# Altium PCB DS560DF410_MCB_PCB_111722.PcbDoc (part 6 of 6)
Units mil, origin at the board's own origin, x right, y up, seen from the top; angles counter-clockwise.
Board outline 5500 x 5000 mil, 6 copper layers (Top Layer, L2_GND1, L3_SIG1, L4_PWR1, L5_GND2, Bottom Layer), stack 61.748 mil thick; 297 components, 231 nets, 1236 pads, 998 vias.
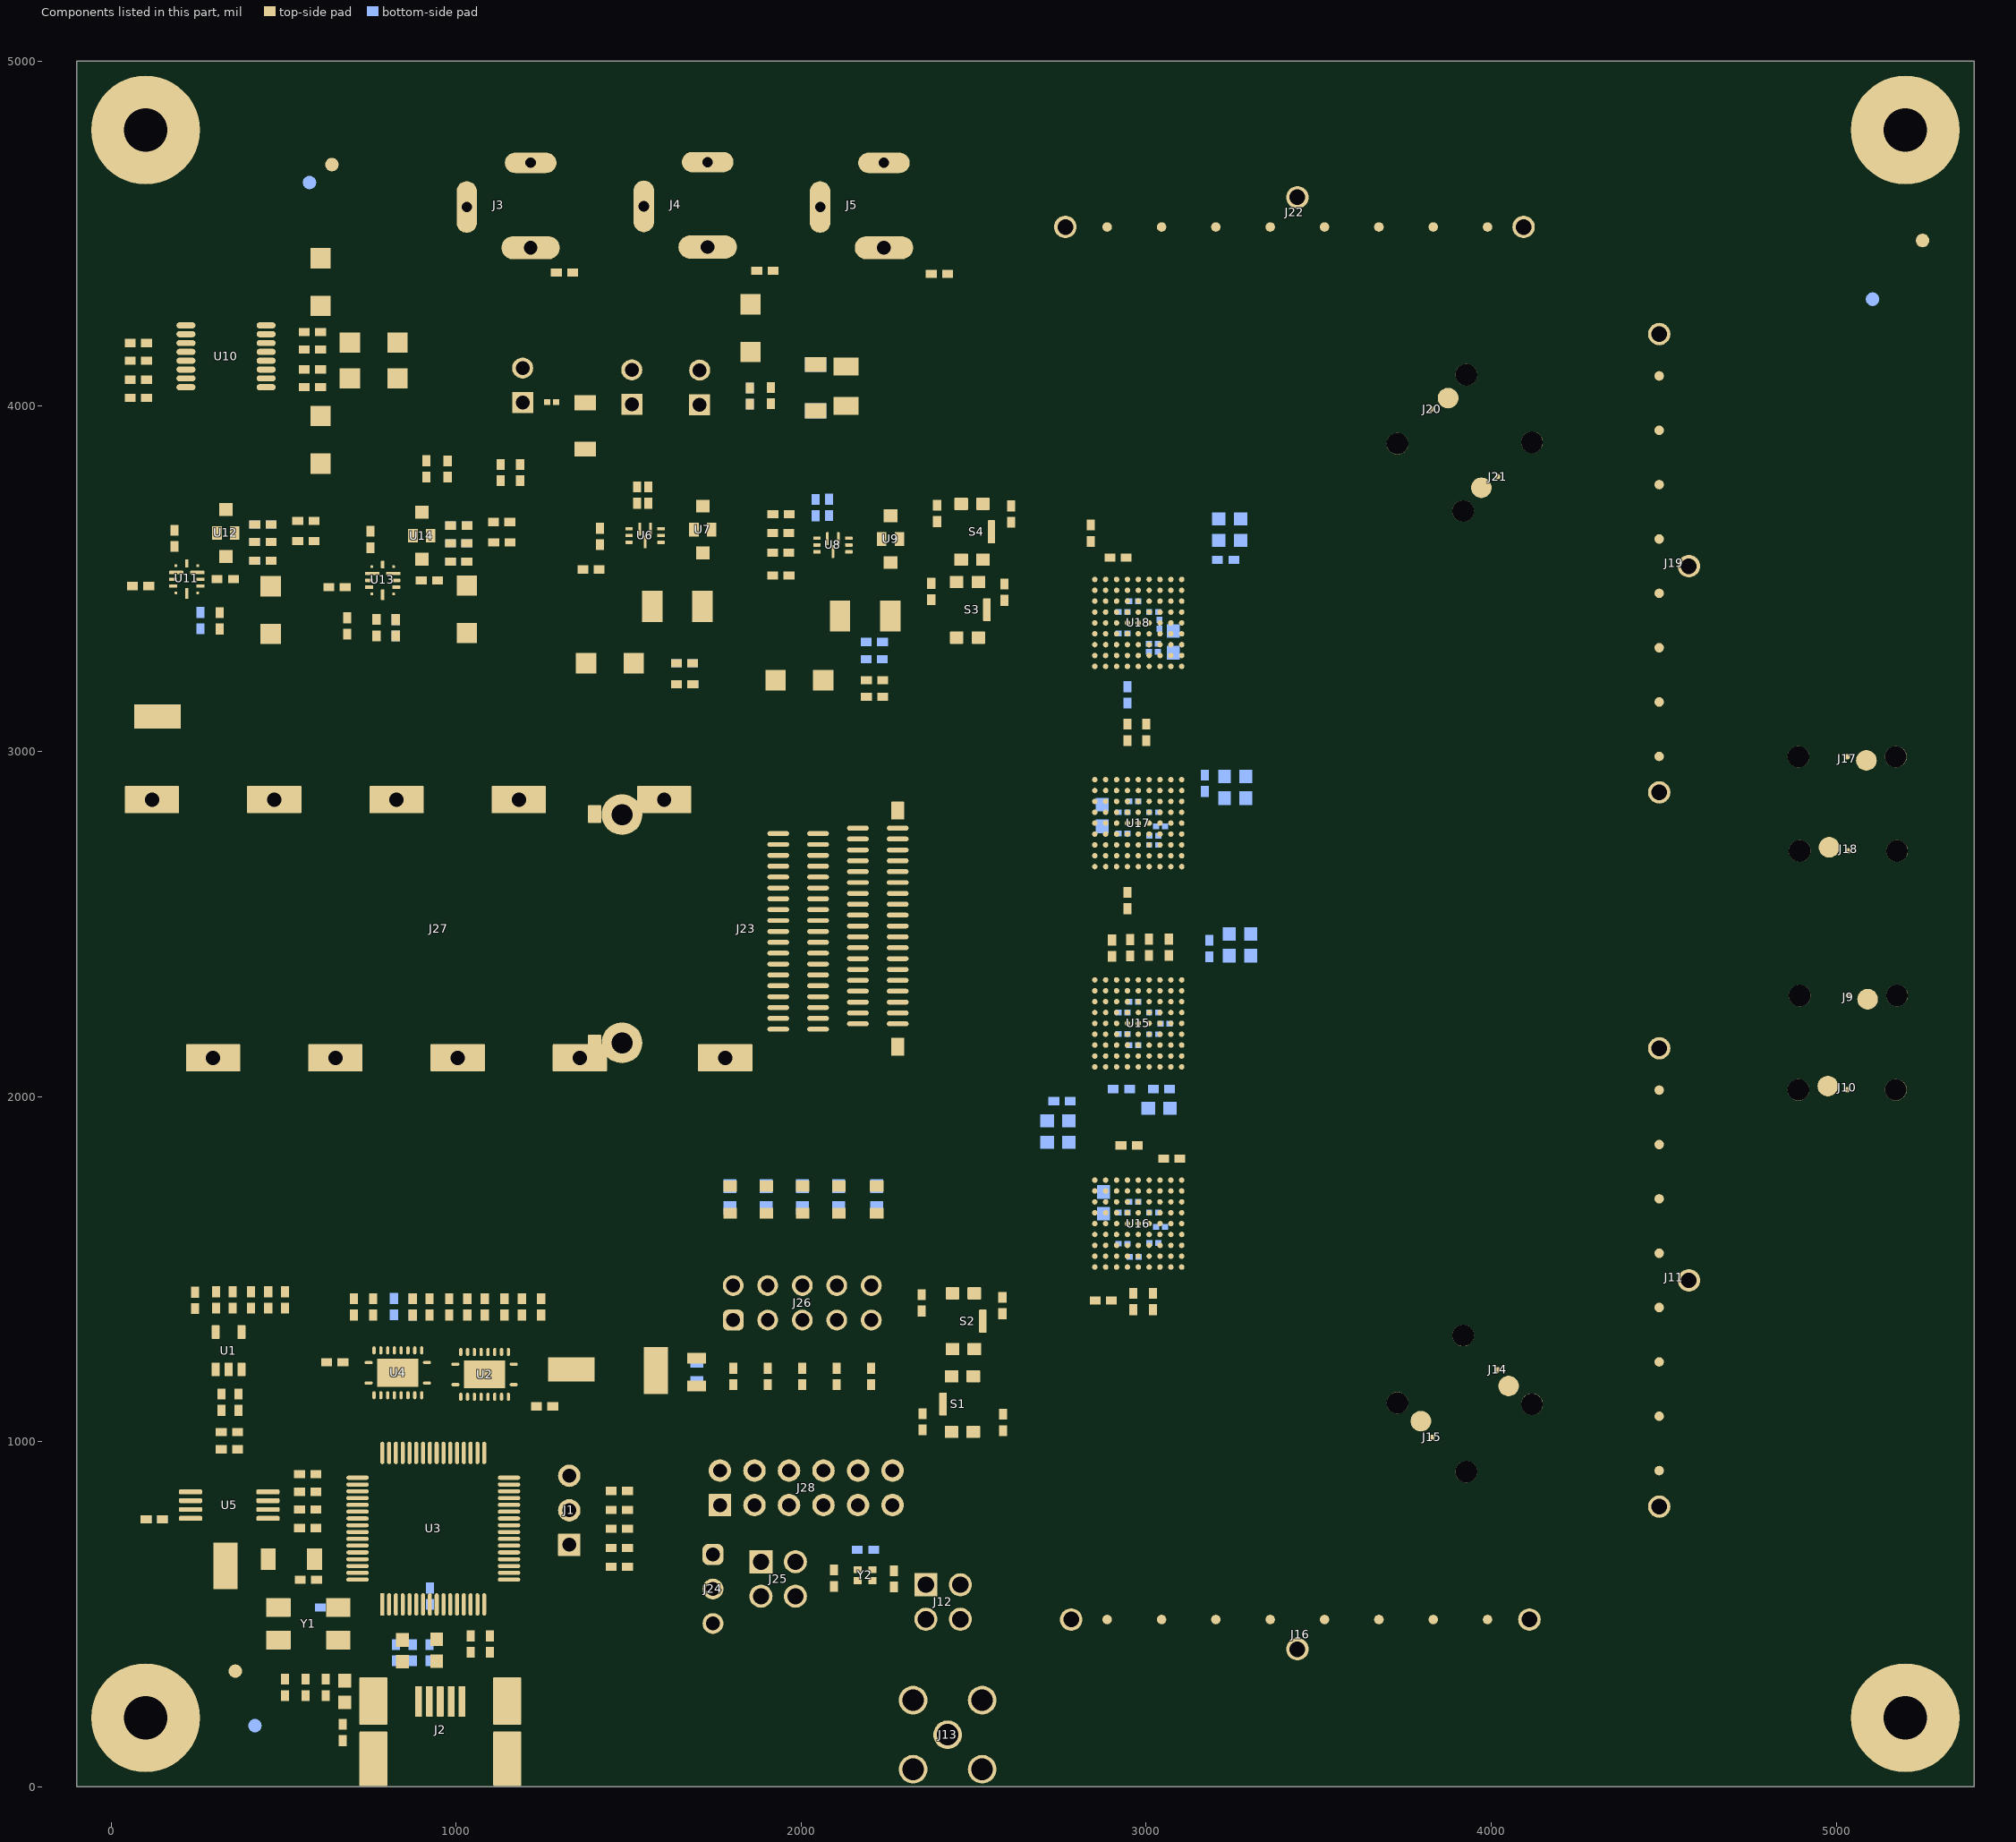
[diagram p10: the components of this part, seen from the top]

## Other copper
Top Layer:
  region net NetL3_1: 825.55,406.42 825.51,446.64 838.75,459.88 838.75,560.33 839.97,561.55 851.14,561.55 851.14,457.51 865.51,443.14 865.51,405.46 862.26,402.21 828.99,402.21 825.55,405.65
  region net 1P8V_CON: 1015.42,3642.39 1015.42,3685.52 1009.26,3691.68 1009.26,3707.28 1012.28,3710.3 1070.15,3710.3 1074.48,3705.97 1074.48,3659.07 1055.87,3640.46 1054.84,3641.5 1016.31,3641.5
  region net 1P2V_CON: 1622,3244.4 1621.9,3317.8 1630.1,3326 1649.6,3326 1656.92,3318.68 1656.92,3246.64 1653.07,3242.8 1623.6,3242.8
  region net VDD_1P8V_2: 894.9,1255.74 894.9,1273.45 907.35,1285.9 930.31,1285.9 935.96,1280.24 935.96,1263.16 925.33,1252.52 898.12,1252.52
  region net 3P3V_VPHY: 775.7,383.2 862.26,383.2 865.51,379.95 865.51,342.64 862.47,339.6 784.81,339.6 772.83,351.57 772.83,380.14 775.65,382.96
  region net 3P3V_VPLL: 924.3,383.2 924.3,324.37 937.66,311.01 952.6,311.01 963.34,321.76 963.34,382.96 959.5,386.8 927.88,386.8 924.29,383.2
  region net NetL4_1: 949.3,498.7 955,493 955,452.9 963.34,444.55 963.34,406.94 962.3,405.9 926.02,405.9 924.29,407.62 924.29,446.16 937.7,459.56 937.7,498.97 937.7,557.6 940.43,560.33 947.16,560.33 949.3,558.18
  region net 5V_USB: 899.4,198.9 845.72,198.9 837.95,206.68 837.95,288.12 845.5,295.67 897.93,295.67 902.2,291.4 902.2,201.7
  region net NetR46_2: 1123.22,3679.06 1094.52,3679.06 1091.02,3675.56 1091.02,3633.36 1076.72,3619.06 1017.32,3619.06 1013.52,3615.26 1013.52,3591.56 1015.92,3589.16 1122.92,3589.16 1128.12,3594.36 1128.12,3674.16
  region net NetC46_1: 829.12,3577.76 932.86,3577.76 947.71,3592.61 947.71,3664.41 955.3,3672 997.7,3672 1002.4,3667.3 1002.4,3536.24 997.22,3531.06 861.92,3531.06 839.62,3508.76 796.92,3508.76 795.92,3509.76 795.92,3521.96 807.52,3533.56 807.52,3556.16
  region net NetR37_2: 208.78,3512.24 168.08,3512.24 164.08,3516.24 164.08,3604.71 169.13,3609.75 195.67,3609.75 197.88,3607.54 197.88,3535.44 210.18,3523.14 210.18,3513.64
  region net NetR45_2: 776.4,3509 735.7,3509 731.7,3513 731.7,3601.47 736.74,3606.51 763.29,3606.51 765.5,3604.3 765.5,3532.2 777.8,3519.9 777.8,3510.4
  region net NetL7_1: 2076.26,3399.83 2076.26,3349.85 2082.58,3343.53 2141.96,3343.53 2146.36,3347.93 2146.36,3399.23 2146.35,3511.73 2096.75,3561.33 2096.76,3596.73 2095.05,3598.43 2088.96,3598.43 2087.36,3596.83 2087.36,3561.93 2076.26,3550.83
  region net NetC38_1: 2212.76,3470.23 2212.76,3145.73 2225.16,3133.33 2278.46,3133.33 2292.16,3147.03 2292.16,3558.23 2282.66,3567.73 2206.26,3567.73 2170.09,3603.89 2128.62,3603.89 2126.06,3601.33 2126.06,3556.93
  region net NetC31_1: 1395.96,4043.08 1538.32,4043.08 1546.1,4035.3 1546.1,3976.3 1537.7,3967.9 1475.2,3967.9 1457,3986.1 1287.1,3986.1 1280.46,3992.74 1280.46,4011.13 1280.46,4029.16 1294.38,4043.08
  region net NetJ7_1: 1265.5,4045.6 1163.2,4045.6 1157.8,4040.2 1157.8,3979.4 1163,3974.2 1262,3974.2 1273,3985.2 1273,4038.1
  region net NetR38_2: 555.6,3682.3 526.9,3682.3 523.4,3678.8 523.4,3636.6 509.1,3622.3 449.7,3622.3 445.9,3618.5 445.9,3594.8 448.3,3592.4 555.3,3592.4 560.5,3597.6 560.5,3677.4
  region net NetC41_1: 229.3,3512 272,3512 294.3,3534.3 429.6,3534.3 434.3,3539 434.3,3667.6 431,3670.9 400.6,3670.9 398.3,3668.6 398.3,3600.2 381.7,3583.6 264.1,3583.6 239.9,3559.4 239.9,3536.8 228.3,3525.2 228.3,3513
  region net NetC34_1: 1668.5,3497.8 1668.5,3179.61 1674.61,3173.5 1739.8,3173.5 1747.9,3181.6 1747.9,3585.8 1738.4,3595.3 1662,3595.3 1625.84,3631.46 1584.36,3631.46 1581.8,3628.9 1581.8,3584.5
  region net NetL6_1: 1532,3427.4 1532,3377.42 1538.32,3371.1 1597.7,3371.1 1602.1,3375.5 1602.1,3426.8 1602.1,3539.3 1552.5,3588.9 1552.5,3624.3 1550.8,3626 1544.7,3626 1543.1,3624.4 1543.1,3589.5 1532,3578.4
  region net VDD_3p3V: 476.95,4224.57 478.2,4224.57 486.58,4232.96 486.58,4244.36 486.58,4264.15 478.91,4271.83 417.93,4271.82 410.76,4264.65 410.76,4244.61 410.76,4231.72 417.9,4224.58
  region net VDD_3p3V: 246.62,4271.83 185.65,4271.82 178.47,4264.65 178.47,4182.02 186.55,4173.95 244.45,4173.95 254.3,4183.8 254.3,4264.15
  region net VDD_1P8V_2: 1002.2,3741.52 1116.38,3741.52 1139.8,3718.1 1139.8,3651.8 1143.18,3648.43 1180.21,3648.43 1198.2,3666.41 1198.2,3718.2 1227,3747 1227,3795.5 1221.75,3800.75 1072.35,3800.75 1059.15,3813.95 898.37,3813.95 878.1,3793.74 878.1,3676.27 882.37,3672 932.67,3672
  region net VDD_3p3V: 2162.68,4032.88 2081.6,4032.88 2073.32,4024.6 1760.55,4024.6 1743.68,4041.48 1673.43,4041.48 1664.82,4032.88 1664.82,3950.7 1679.72,3935.8 2161.68,3935.8 2170.83,3944.95 2170.82,4024.73
  region net VDD_3p3V: 1511.68,3639.5 1440.4,3639.5 1429.7,3628.8 1381.04,3628.8 1352.3,3657.54 1352.3,3708.89 1378.86,3735.45 1492.75,3735.45 1569.5,3735.45 1571.62,3733.32 1571.62,3702.93 1568.4,3699.7 1548.2,3699.7 1536.6,3688.1 1536.6,3625.98 1535.03,3624.4 1526.78,3624.4
  region net 3P3V_VPHY: 336.97,1038.82 333.35,1042.45 281.92,1042.45 275.3,1035.82 275.3,970.18 282.6,962.88 333.7,962.88 336.97,966.15
  region net VDD_1P8V_2: 758.35,1237.2 752.07,1243.47 656.53,1243.47 654.18,1241.12 654.18,1203.22 665.8,1191.6 747.6,1191.6 758.35,1202.35
  region net 1P8V_FTDI: 630,697.68 570.68,697.68 564.03,691.03 564.03,627.28 577.53,613.78 577.53,588.2 581.8,583.93 620.32,583.93 627.93,591.53 627.93,618.38 636.57,627.02 636.57,691.1
  region net 5V_USB: 313.8,1230.5 290.53,1230.5 287.4,1227.38 287.4,1127.78 295.75,1119.43 385.95,1119.43 394.5,1127.97 394.5,1225.43 388.82,1231.1 367.35,1231.1 364.75,1228.5 364.75,1187.15 356.62,1179.03 326.35,1179.02 315.6,1189.77 315.6,1228.7
  region net 5V_USB: 694.82,267.47 655.95,267.47 653.03,264.55 653.03,168.62 657.75,163.9 692.78,163.9 698.95,170.07 698.95,263.35
  region net 3P3V_FTDI: 262.1,785.12 168.33,785.12 165.6,787.85 133.08,787.85 131.15,785.93 131.15,744.22 139.35,736.03 255.5,736.03 264.42,744.95 264.42,782.8
  region net 3P3V_FTDI: 744.45,881.88 581.95,881.88 575.5,875.43 575.5,738.4 579.3,734.6 657.22,734.6 674.25,751.62 744.03,751.62 747.12,754.72 747.12,760.57 743.97,763.72 655.28,763.72 646.07,772.93 646.29,858.07 657.62,869.4 744.5,869.4 747.15,872.05 747.15,879.17
  region net 3P3V_FTDI: 419.95,1402.4 418.07,1404.27 232.88,1404.28 226.42,1397.82 226.42,1301.28 236.1,1291.6 312.2,1291.6 317.45,1296.85 317.45,1330.18 330.88,1343.6 414.45,1343.6 419.95,1349.1
  region net 3P3V_VPLL: 514.62,1476.55 398.28,1476.55 389.85,1468.12 389.85,1420.38 393.68,1416.55 516.97,1416.55 520.68,1420.25 520.68,1470.5
  region net GND: 838.04,3462.49 806.47,3462.49 796.92,3472.04 777.32,3472.04 766.82,3461.54 736.42,3461.54 734.29,3459.41 734.29,3413.66 739.97,3407.98 834.87,3407.97 841.39,3414.49 841.39,3459.14
  region net GND: 270.42,3465.72 238.85,3465.73 229.3,3475.27 209.7,3475.27 199.2,3464.77 168.8,3464.77 166.67,3462.65 166.67,3393.73 174.62,3385.77 271.62,3385.77 273.78,3387.93 273.78,3462.38
  pour cut-out: 2241.23,2700.26 2241.23,2759.93 2312.22,2759.93 2312.22,2700.26
  pour cut-out: 2241.23,2605.77 2241.23,2665.44 2312.22,2665.44 2312.22,2605.77
  pour cut-out: 2125.87,2700.26 2125.87,2759.93 2196.87,2759.93 2196.87,2700.26
  pour cut-out: 2125.87,2605.77 2125.87,2665.44 2196.87,2665.44 2196.87,2605.77
  pour cut-out: 1972.16,2684.51 1972.16,2744.18 1901.16,2744.18 1901.16,2684.51
  pour cut-out: 1972.16,2590.02 1972.16,2649.69 1901.16,2649.69 1901.16,2590.02
  pour cut-out: 2010.52,2684.51 2010.52,2744.18 2081.51,2744.18 2081.51,2684.51
  pour cut-out: 2010.52,2590.02 2010.52,2649.69 2081.51,2649.69 2081.51,2590.02
  pour cut-out: 2241.23,2287.49 2241.23,2227.82 2312.22,2227.82 2312.22,2287.49
  pour cut-out: 2241.23,2381.98 2241.23,2322.31 2312.22,2322.31 2312.22,2381.98
  pour cut-out: 2125.87,2287.49 2125.87,2227.82 2196.87,2227.82 2196.87,2287.49
  pour cut-out: 2125.87,2381.98 2125.87,2322.31 2196.87,2322.31 2196.87,2381.98
  pour cut-out: 2010.52,2366.23 2010.52,2306.56 2081.51,2306.56 2081.51,2366.23
  pour cut-out: 2010.52,2271.74 2010.52,2212.07 2081.51,2212.07 2081.51,2271.74
  pour cut-out: 1895.17,2271.74 1895.17,2212.07 1966.16,2212.07 1966.16,2271.74
  pour cut-out: 1895.17,2366.23 1895.17,2306.56 1966.16,2306.56 1966.16,2366.23
  text ".Layer_Name" at -423,-1858.49 h60
L2_GND1:
  text ".Layer_Name" at -423,-1858.49 h60
L3_SIG1:
  text ".Layer_Name" at -423,-1858.49 h60
L4_PWR1:
  text ".Layer_Name" at -423,-1858.49 h60
L5_GND2:
  text ".Layer_Name" at -423,-1858.49 h60
Bottom Layer:
  region net VDD_1P8V_1: 2948.21,2196.07 2942.56,2201.73 2942.56,2208.94 2947.45,2213.83 3027.43,2213.83 3032.28,2218.68 3051.09,2218.68 3052.26,2217.5 3052.26,2202.8 3045.54,2196.07
  region net VDD_3p3V: 2012.53,3638.65 2002.05,3649.13 2002.05,3689.48 2012.8,3700.23 2093.95,3700.22 2093.95,3651.73 2080.88,3638.65
  region net VDD_3p3V: 2060.95,4023.6 1780.32,4023.6 1766.82,4010.1 1766.82,3948.9 1779.85,3935.88 2069.22,3935.87 2076.65,3943.3 2076.65,4007.9
  text ".Layer_Name" at -423,-1858.49 h60
Multi-Layer:
  pour cut-out: 2168.77,2336.39 2168.77,2367.89 cw(c2188.87,2367.89) 2208.96,2367.89 2208.96,2336.39 cw(c2188.87,2336.39)
  pour cut-out: 2284.12,2336.39 2284.12,2367.89 cw(c2304.22,2367.89) 2324.32,2367.89 2324.32,2336.39 cw(c2304.22,2336.39)
  pour cut-out: 2282.78,2241.78 2282.78,2273.28 cw(c2302.87,2273.28) 2322.97,2273.28 2322.97,2241.78 cw(c2302.87,2241.78)
  pour cut-out: 2168.77,2619.86 2168.77,2651.35 cw(c2188.87,2651.35) 2208.96,2651.35 2208.96,2619.86 cw(c2188.87,2619.86)
  pour cut-out: 2284.12,2619.86 2284.12,2651.35 cw(c2304.22,2651.35) 2324.32,2651.35 2324.32,2619.86 cw(c2304.22,2619.86)
  pour cut-out: 2284.12,2714.35 2284.12,2745.84 cw(c2304.22,2745.84) 2324.32,2745.84 2324.32,2714.35 cw(c2304.22,2714.35)
  pour cut-out: 2168.77,2241.91 2168.77,2273.4 cw(c2188.87,2273.4) 2208.96,2273.4 2208.96,2241.91 cw(c2188.87,2241.91)
  pour cut-out: 2168.77,2714.35 2168.77,2745.84 cw(c2188.87,2745.84) 2208.96,2745.84 2208.96,2714.35 cw(c2188.87,2714.35)

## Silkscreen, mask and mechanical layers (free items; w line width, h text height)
Top Overlay:
  lines w5: 252,3944 477,3944 477,3741 ; 405,3741 505.17,3741 505.17,3523 479,3523 ; 482,4518 482,4296 540,4296 540,4245 ; 538,183 538,224 ; 643,224 472,224 472,345 711,345 711,302 ; 959.59,3684.74 1062.7,3684.74 1062.7,3567 1122.62,3567 ; 966,3410 966,3461 ; 1122,3567 1160,3567 ; 1255.9,797.5 1268.4,797.5 ; 1670.9,548 1686.2,548 ; 1670.9,648 1686.2,648 ; 1704.2,567.7 1686.2,567.7 1686.2,531.7 1818.1,531.7 ; 1704.2,667.7 1686.2,667.7 1686.2,631.7 1818.1,631.7 ; 1803.16,753.85 1827.22,745.26 2336.2,745.26 2336.2,813.36 2505.88,813.36 ; 1987.9,479.1 1989.7,427.9 ; 2360.2,416.1 2360.2,387.5 2466.4,387.5 2466.4,414.6 ; 2378.7,661.1 2405.69,695.84 ; 2415.3,366.9 2415.3,387.8 ; 2521.5,589.6 2550.2,589.6 ; 2505.88,813.36 2505.88,771.63 2839.15,771.63 2839.15,1353.99 2702.61,1353.99 2702.61,972.2 2505.88,972.2 2505.88,813.36 ; 141,3780 252,3780 252,3945.2 141,3945.2 141,3780 ; 384,77 585,77 585,183 384,183 384,77 ; 426,4518 544,4518 544,4736 426,4736 426,4518 ; 526,4024.4 640,4024.4 640,4245 526,4245 526,4024.4 ; 1160,3422.3 1271,3422.3 1271,3574.3 1160,3574.3 1160,3422.3
  text "'.PRJ_Number'.PCB_Rev" at 2773.5,4869.1 h108.27
  text "+1.2V" at 2038.8,4797.7 h35 r90
  text "+1.8V" at 1530.7,4791.9 h35 r90
  text "+3.3V" at 1020.1,4789.9 h35 r90
  text "ModSelL" at 1869,1051.14 h35 r90
  text "ResetL" at 1969,1051.14 h35 r90
  text "ModPrsL" at 2069,1051.14 h35 r90
  text "LPMode/TxDis" at 2302.6,1013.84 h35 r90
  text "IntL/RxLOS" at 2164.72,983.18 h32 r90
  text "GND" at 1399.97,905.48 h35
  text "P/VS4" at 2565.57,790.94 h35 r90
  text "P/VS1" at 2614.94,790.94 h35 r90
  text "P/VS2" at 2663.93,790.94 h35 r90
  text "P/VS3" at 2714.61,790.94 h35 r90
  text "QSFP-DD_RESERVED" at 2766.2,790.94 h35 r90
  text "ePPS/CLOCK" at 2825.42,790.94 h35 r90
  text "25MHZ_CLK" at 2352.85,719.26 h35
  text "QSFP_SDA" at 2049.9,684.7 h35
  text "FTDI_SDOUT" at 1244.05,620.28 h35 r90
  text "MAIN_SDA" at 1647.04,581.6 h35 r90
  text "MAIN_SCL" at 1375.6,528.6 h35
  text "EXT_SMA" at 2590.57,461.52 h35 r90
  text "GND" at 1592.3,447.2 h35
  text "QSFP_SCL" at 1906.07,374.86 h35
  text "FTDI_SCLK" at 1336.65,326.92 h35 r90
  text "CAL_CLK_IN" at 2200,318.3 h35
  text ".Layer_Name" at -423,-1858.49 h60
Bottom Overlay:
  lines w5: 2916.89,2848.3 2916.89,2880.7 ; 2924.9,1684.9 2924.9,1716.2
  text "APR- 2022" at 1562.8,248 h50
  text "305-PD-22-0294" at 1265,143 h50
  text ".Layer_Name" at -423,-1858.49 h60
Top Paste:
  text ".Layer_Name" at -423,-1858.49 h60
Bottom Paste:
  text ".Layer_Name" at -423,-1858.49 h60
Top Solder:
  text ".Layer_Name" at -423,-1858.49 h60
  text ".Layer_Name" at -423,-1858.49 h60
Bottom Solder:
  text ".Layer_Name" at -423,-1858.49 h60
Drill Guide:
  text ".Layer_Name" at -423,-1858.49 h60
M1 Board Outline:
  the board outline again, w10
  text ".Layer_Name" at -423,-1858.49 h60
M2 Board Dimensions:
  rectangle: 16.32,-422.92 141.32,-297.92
  rectangle: 141.32,-547.92 516.32,-422.92
  lines w7: 16.32,-422.92 1016.32,-422.92 ; 141.32,-547.92 141.32,-297.92 ; 266.32,-547.92 266.32,-297.92 ; 516.32,-547.92 516.32,-297.92 ; 766.32,-547.92 766.32,-297.92 ; 16.32,-547.92 1016.32,-547.92 1016.32,-297.92 16.32,-297.92 16.32,-547.92
  text ".Layer_Name" at -423,-1858.49 h60
M3 3D STEP Top:
  text ".Layer_Name" at -423,-1858.49 h60
M4 3D STEP Bottom:
  text ".Layer_Name" at -423,-1858.49 h60
M5 Assembly Top:
  lines w10: -1292,-1930.17 5308,-1930.17 ; -1292,-1726.83 5310,-1726.83 ; -1292,-1523.5 -1292,-2133.5 2713,-2133.5 5310,-2133.5 5310,-1523.5 -1291.5,-1523.5 -1291.5,-2133.5 284,-2133.5 ; 1173,-2133.5 1173,-1523.5 ; 2440,-1726.83 2440,-1523.5 ; 3280,-1726.83 3280,-1523.5 ; 3902,-2140 3902,-1937.17
  text "COMPONENTS MARKED 'DNP' SHOULD NOT BE POPULATED." at 153.5,-1318.5 h60
  text "ASSEMBLY VARIANT:" at 153,-1434 h60
  text ".VariantName" at 1189,-1434 h60
  text "PCB VIEWED FROM TOP SIDE" at -1228.5,-1655.67 h60
  text "BOARD #:" at 1248,-1655.67 h60
  text ".PRJ_Number" at 1793.5,-1655.67 h60
  text "REV:" at 2638,-1655.67 h60
  text ".PCB_Rev" at 2929.5,-1655.67 h60
  text "SVN REV:" at 3476,-1655.67 h60
  text ".VersionControl_RevNumber" at 3982,-1655.67 h60
  text "TID #:" at 1248,-1859 h60
  text ".TID" at 1793.5,-1859 h60
  text "PLOT NAME =" at -1228.5,-2064.34 h60
  text ".plot_File_Name" at -423,-2064.34 h60
  text "GENERATED    :" at 1250,-2064.34 h60
  text ".Print_Date" at 2119.5,-2064.34 h60
  text ".Print_Time" at 2848.5,-2064.34 h60
  text "TEXAS INSTRUMENTS" at 4113,-2064.34 h60
M6 Assembly Bottom:
  lines w10: -1292.5,-1727.33 5309.5,-1727.33 ; -1290.5,-1930.67 5309.5,-1930.67 ; 115.5,-2140.5 115.5,-1937.67 ; 737.5,-1727.33 737.5,-1524 ; 1577.5,-1727.33 1577.5,-1524 ; 2844.5,-2134 2844.5,-1524 ; 3733.5,-2134 5309,-2134 5309,-1524 -1292.5,-1524 -1292.5,-2134 1304.5,-2134 5309.5,-2134 5309.5,-1524
  text "COMPONENTS MARKED 'DNP' SHOULD NOT BE POPULATED." at 5102,-1318 h60
  text ".VariantName" at 4058,-1434 h60
  text "ASSEMBLY VARIANT:" at 5097,-1434 h60
  text ".VersionControl_RevNumber" at 35.5,-1656.17 h60
  text "SVN REV:" at 541.5,-1656.17 h60
  text ".PCB_Rev" at 1088,-1656.17 h60
  text "REV:" at 1379.5,-1656.17 h60
  text ".PRJ_Number" at 2224,-1656.17 h60
  text "BOARD #:" at 2769.5,-1656.17 h60
  text "PCB VIEWED FROM BOTTOM SIDE" at 5246,-1656.17 h60
  text ".TID" at 2224,-1859.5 h60
  text "TID #:" at 2769.5,-1859.5 h60
  text "TEXAS INSTRUMENTS" at -95.5,-2064.84 h60
  text ".Print_Time" at 1169,-2064.84 h60
  text ".Print_Date" at 1898,-2064.84 h60
  text "GENERATED    :" at 2767.5,-2064.84 h60
  text ".plot_File_Name" at 4440.5,-2064.84 h60
  text "PLOT NAME =" at 5246,-2064.84 h60
M9 Title Sheet:
  drawing of 57 lines, arcs and shapes, not listed
  text "1" at -260.16,12036.5 h70
  text "2" at 2235.5,12036.5 h70
  text "3" at 4724.84,12036.5 h70
  text "4" at 7231.51,12036.5 h70
  text "5" at 9730.5,12036.5 h70
  text "6" at 12235.5,12036.5 h70
  text "A" at -1416.5,5893.5 h70
  text "A" at 21383.5,5893.5 h70
  text "B" at -1416.5,3513.5 h70
  text "B" at 21383.5,3513.5 h70
  text "C" at -1416.5,1138.5 h70
  text "C" at 21383.5,1138.5 h70
  text "PROJECT TITLE:" at 18343.5,-722.5 h45
  text ".PRJ_Title" at 18393.5,-855.83 h70
  text "DESIGNED FOR:" at 18343.5,-1023.5 h45
  text ".PRJ_Customer" at 18393.5,-1163.5 h70
  text "D" at -1416.5,-1231.5 h70
  text "D" at 21383.5,-1231.5 h70
  text "FILE NAME:" at 18343.5,-1323.5 h45
  text ".PCB_File_Name_No_Path" at 18393.5,-1443.5 h70
  text "Texas Instruments (TI) and/or its licensors do not warrant the accuracy or completeness of this specification" at 5374,-1605.34 h45
  text "ENGINEER:" at 18343.5,-1613.5 h45
  text "LAYOUT BY:" at 19848.5,-1613.5 h45
  text "or any information contained therein. TI and/or its licensors do not warrant that this design will meet" at 5329.01,-1718 h45
  text ".PRJ_Engineer" at 18393.5,-1768.49 h60
  text ".PCB_Layout" at 19899,-1768.49 h70
  text "the specifications, will be suitable for your application or fit for any particular purpose, or will operate in" at 5329.01,-1830.67 h45
  text ".Layer_Name" at -423,-1858.49 h60
  text "ALTIUM DESIGNER VERSION:" at 19848.5,-1923.5 h45
  text "an implementation. TI and/or its licensors do not warrant that the design is production worthy. You should" at 5329.01,-1943.33 h45
  text "completely validate and test your design implementation to confirm the system functionality for your application." at 5374,-2056 h45
  text ".print_Scale" at 18393.5,-2056.83 h70
  text ".Application_BuildNumber" at 19899,-2056.83 h70
  text "1" at -260.16,-2263.5 h70
  text "2" at 2235.5,-2263.5 h70
  text "3" at 4724.84,-2263.5 h70
  text "4" at 7231.51,-2263.5 h70
  text "5" at 9730.5,-2263.5 h70
  text "6" at 20235.5,-2263.5 h70
M10 Fab Notes:
  drawing of 189 lines, arcs and shapes, not listed
  text "DESIGN INFORMATION" at 19382.02,5356.17 h60
  text "MIN. TRACK WIDTH:" at 18737.46,5224.05 h60
  text "6" at 19833.7,5224.05 h60
  text "MIL" at 19988.46,5224.05 h60
  text "4.68" at 19735,5102 h60
  text "MIL" at 19988.46,5100.92 h60
  text "MIN. CLEARANCE:" at 18737.46,5099.92 h60
  text "IMPEDANCE DETAILS." at 12254.32,5073.21 h75
  text "MIN. VIA PAD SIZE:" at 18737.46,4975.8 h60
  text "14" at 19803.71,4975.8 h60
  text "MIL" at 19988.46,4975.8 h60
  text "1. ALL 6 MIL TRACES WITH 12 MIL AIRGAP ON TOP AND BOTTOM LAYERS" at 12254.32,4891.24 h75
  text "0.05mm (2MIL)" at 19432.46,4845.9 h60
  text "MINIMUM ANNULAR RING" at 18408.23,4837.67 h60
  text "EXTERNAL" at 20140.46,4837.67 h60
  text "PER" at 18608.23,4727.55 h60
  text "IPC-D-275 CLASS 2 LEVEL C" at 18828.23,4727.54 h60
  text "NEED 100 ohm +/-5% IMPEDANCE WITH 6 MIL COPLANAR SPACING" at 12399.32,4701.24 h75
  text "MIL, HOLES" at 20316.46,4627.07 h60
  text "+/-" at 19924,4618.48 h60
  text "+/-" at 20778,4618.48 h60
  text "REGISTRATION TOLERANCES:" at 18408.23,4617.42 h60
  text "METAL" at 19608,4617.42 h60
  text "5" at 20184.2,4617.42 h60
  text "3" at 21017.2,4617.42 h60
  text "MIL" at 21133.46,4617.42 h60
  text "2. ALL 7.3 MIL TRACES ON TOP LAYER  NEED 50 ohm +/-5% IMPEDANCE" at 12247.32,4524.13 h75
  text "HOLE SIZE TOLERANCE (UNLESS OTHERWISE SPECIFIED):" at 18408.23,4519.1 h60
  text "+/-" at 20778,4516.23 h60
  text "3" at 21017.2,4515.17 h60
  text "MIL" at 21133.46,4515.17 h60
  text "MATERIAL:" at 18333.46,4377.52 h60
  text "3. ALL 7.3 MIL TRACES ON BOTTOM LAYER  NEED 50 ohm +/-5% IMPEDANCE" at 12247.32,4348.76 h75
  text "FR-4 High Tg" at 19319.9,4249 h60
  text "RO4350B+185HR" at 20566.46,4242.06 h60
  text "X" at 20064.46,4241.01 h60
  text "FR-408" at 18754.46,4236.49 h60
  text "OTHER" at 20242.46,4236.49 h60
  text "4. ALL 9.4 MIL TRACES ON L3_SIG1 LAYER NEED 50 ohm +/-5% IMPEDANCE" at 12247.32,4160.13 h75
  text "62 MIL (1.6mm) +/-10%" at 19074.56,4093.46 h60
  text "X" at 18954.46,4091.01 h60
  text "THICKNESS:" at 18408.23,4085.24 h60
  text "OTHER" at 20359.46,4085.24 h60
  text "TOLERANCE:" at 18408.23,3946.92 h60
  text "X" at 19256.46,3946.92 h60
  text "ANSI IPC-6012 TYPE 3 CLASS 2" at 19434.48,3946.92 h60
  text "5. ALL 6.4 MIL TRACES ON BOTTOM LAYER NEED 50 ohm +/-5% IMPEDANCE" at 12248.69,3943.74 h75
  text "OTHER +/-" at 19434.46,3802.73 h60
  text "WITH 6 MIL COPLANAR SPACING" at 12400.67,3753.74 h75
  text "BOW & TWIST:" at 18408.23,3657.54 h60
  text "X" at 19256.46,3657.54 h60
  text "ANSI IPC-6012 TYPE 3 CLASS 2" at 19434.48,3657.54 h60
  text "6. ALL 7 MIL TRACES WITH 8 MIL AIRGAP ON TOP AND BOTTOM LAYERS" at 12260.32,3585.24 h75
  text "OTHER +/-" at 19434.46,3510.85 h60
  text "NEED 90 ohm +/-5% IMPEDANCE WITH 8 MIL COPLANAR SPACING" at 12405.32,3395.24 h75
  text "DRILLING:" at 18333.46,3380.23 h60
  text "NC_DRILL FILES" at 20094.46,3275.04 h60
  text "REFERENCE:" at 18408.23,3271.1 h60
  text "X" at 19065.46,3271.01 h60
  text "AS SHOWN" at 19243.46,3271.1 h60
  text "X" at 19966.46,3271.1 h60
  text "FAB NOTES :" at 12285.99,3197.28 h75
  text "OTHER" at 20392.46,3128.85 h60
  text "PTH COPPER THICKNESS:" at 18407.91,3125.32 h60
  text "X" at 19547.14,3125.32 h60
  text "20-30 um" at 19675.14,3125.32 h60
  text "7. ALL 7.874 , 7.9 , 8.1 AND 10.1 MIL DRILL NEEDS TO BE NON CONDUCTIVE" at 12286.07,3062.77 h75
  text "BOARD FINISH:" at 18333.46,2977.73 h60
  text "VIA FILLING AND PLATED OVER FROM TOP SIDE" at 12506.07,2877.77 h75
  text "SILKSCREEN:" at 18488.68,2867.6 h60
  text "X" at 19446.46,2867.6 h60
  text "TOP" at 19563.46,2867.6 h60
  text "X" at 19956.46,2867.6 h60
  text "BOTTOM" at 20074.46,2867.6 h60
  text "(SMOOTH FINISH THESE HOLES ON BOTH SIDE AFTER THE CONDUCTIVE FILLING)" at 12463,2714.15 h75
  text "SILKSCREEN COLOR:" at 18488.68,2712.41 h60
  text "X" at 19445.46,2712.41 h60
  text "WHITE" at 19563.46,2712.41 h60
  text "OTHER" at 20074.46,2712.41 h60
  text "X" at 19576.46,2568.96 h60
  text "GREEN" at 19694.46,2568.96 h60
  text "OTHER" at 20312.46,2568.96 h60
  text "SOLDER RESIST COLOR:" at 18488.68,2562.1 h60
  text "8. ALL HOLES SHOULD BE FHS." at 12292.07,2535.42 h75
  text "X" at 19576.46,2414.71 h60
  text "MATTE" at 19694.46,2414.71 h60
  text "SEMI-GLOSS" at 20312,2414.07 h60
  text "9. NO VENDOR LOGO OR NAME ON THE BOARD." at 12292.07,2357.82 h75
  text "IMMERSION GOLD (ENIG)" at 19394.46,2241.94 h60
  text "ENEPIG" at 20732,2234.72 h60
  text "SURFACE FINISH:" at 18333.46,2233.72 h60
  text "X" at 19216.46,2233.72 h60
  text "10. REMOVE ALL UNUSED PADS IN ALL INNER LAYERS" at 12292.07,2198.89 h75
  text "IMM. TIN/SILVER OR EQUIV" at 18663,2096.4 h60
  text "OTHER" at 20094.46,2092.47 h60
  text "11. CLIP THE SILK ON NO MASK AREA." at 12292.73,2037.63 h75
  text "ARRAY/PANEL:" at 18333.46,1937.09 h60
  text "X" at 19216.46,1932.9 h60
  text "CUT AND TRIM PER M1 BOARD OUTLINE" at 19394.46,1928.87 h60
  text "12. 8 MIL AND 10 MIL DRILL VIAS NEED NON CONDUCTIVE" at 12290.82,1853.72 h75
  text "N.C. ROUTE" at 19394.46,1792.9 h60
  text "V. SCORE" at 20260.46,1792.9 h60
  text "VIA PLUGGING FROM BOTTOM SIDE." at 12494.88,1690.46 h75
  text "CERTIFICATION:" at 18333.46,1663.77 h60
  text "MATERIALS AND WORKMANSHIP FOR ALL PCBS" at 19058.46,1663.77 h60
  text "TO MEET OR EXCEED THE REQUIREMENTS OF:" at 19058.46,1569.71 h60
  text "X" at 18695.97,1441.08 h60
  text "ANSI IPC-A-600F CLASS ->" at 18823.96,1441.08 h60
  text "X" at 20471.97,1441.08 h60
  text "2" at 20581.96,1441.08 h60
  text "1" at 20266.96,1439.58 h60
  text "3" at 20935.96,1439.58 h60
  text "X" at 19507.97,1293.39 h60
  text "RoHS" at 19635.96,1293.39 h60
  text "OTHER" at 20280.36,1293.39 h60
  text "PER ORDER" at 20677.42,1293.39 h60
  text "ALL BOARDS MUST MEET OR EXCEED UL94-V0 REQUIREMENTS." at 18361,1139.57 h60
  text "PCB MUST BEAR THE UL94V-0 UL REGISTERED MATERIAL ID NUMBER" at 18361,1023.5 h60
  text "ADDITIONAL REQUIREMENTS:" at 18333.46,854.08 h60
  text "MICROSECTION:" at 18408.23,746.95 h60
  text "YES" at 19313.96,746.95 h60
  text "REQUIRED" at 20175.46,602.62 h60
  text "BARE BOARD ELEC. TEST:" at 18408.23,599.76 h60
  text "NONE" at 19713.96,599.76 h60
  text "X" at 20057.46,599.76 h60
  text "PER ORDER" at 20767.46,599.76 h60
  text "XX MIL VIAS REQUIRE NON-CONDUCTIVE FILL AND PLANARIZE" at 18576.38,394.82 h59
  text "XX MIL VIAS REQUIRE CONDUCTIVE FILL AND PLANARIZE" at 18584.38,290.84 h60
  text "OUTER XX MIL TRACES REQUIRE 50 OHM SINGLE-ENDED IMPEDANCE" at 18583.39,127.46 h58
  text "LAYER 2 & 3 (INNER LAYERS) XX MIL WIDE, XX MIL SPACE / TRACES REQUIRE 100 OHM DIFFERENTIAL IMPEDANCE" at 18575.39,-108.26 h60
  text ".Layer_Name" at -423,-1858.49 h60
M11 Gerber Information:
  circle w10: c6143.44,-396.04 r34.79
  circle w10: c6143.84,-396.1 r65
  circle w10: c6143.44,5332.96 r34.79
  circle w10: c6143.84,5332.9 r65
  circle w10: c-459.82,5332.96 r34.79
  circle w10: c-459.43,5332.9 r65
  lines w10: -1292,-1930.17 5308,-1930.17 ; -1292,-1726.83 5310,-1726.83 ; -1292,-1523.5 -1292,-2133.5 2713,-2133.5 5310,-2133.5 5310,-1523.5 -1291.5,-1523.5 -1291.5,-2133.5 284,-2133.5 ; -567.05,5333.7 -363.78,5333.7 ; -461.02,5239.63 -461.02,5430.96 ; 1173,-2133.5 1173,-1523.5 ; 2440,-1726.83 2440,-1523.5 ; 3280,-1726.83 3280,-1523.5 ; 3902,-2140 3902,-1937.17 ; 6036.22,-395.3 6239.48,-395.3 ; 6036.22,5333.7 6239.48,5333.7 ; 6142.24,-489.37 6142.24,-298.04 ; 6142.24,5239.63 6142.24,5430.96
  text "ALL ARTWORK VIEWED FROM TOP SIDE" at -1228.5,-1655.67 h60
  text "BOARD #:" at 1248,-1655.67 h60
  text ".PRJ_Number" at 1793.5,-1655.67 h60
  text "REV:" at 2638,-1655.67 h60
  text ".PCB_Rev" at 2929.5,-1655.67 h60
  text "SVN REV:" at 3476,-1655.67 h60
  text ".VersionControl_RevNumber" at 3982,-1655.67 h60
  text "LAYER NAME =" at -1228.5,-1858.49 h60
  text "TID #:" at 1248,-1859 h60
  text ".TID" at 1793.5,-1859 h60
  text ".plot_File_Name" at -554,-2056 h40
  text "PLOT NAME =" at -1228.5,-2064.34 h60
  text "GENERATED    :" at 1250,-2064.34 h60
  text ".Print_Date" at 2119.5,-2064.34 h60
  text ".Print_Time" at 2848.5,-2064.34 h60
  text "TEXAS INSTRUMENTS" at 4113,-2064.34 h60
M12 Stackup:
  drawing of 405 lines, arcs and shapes, not listed
  text "STACK UP :" at 12366.1,11334.5 h75
  text "0.5 Oz + PLATING" at 17007,11218.19 h35
  text "Layer" at 12394.58,11166.5 h60
  text "Name" at 12804.49,11166.5 h60
  text "Material" at 13734.23,11166.5 h60
  text "Thickness" at 14594,11166.5 h60
  text "Constant" at 15243.84,11166.5 h60
  text "Board Layer Stack" at 15813.7,11166.5 h60
  text "Top Overlay" at 12804.49,11046.5 h60
  text "Top Solder" at 12804.49,10926.5 h60
  text "Solder Resist" at 13734.23,10926.5 h60
  text "0.40mil" at 14594,10926.5 h60
  text "3.5" at 15243.84,10926.5 h60
  text "1" at 12394.58,10806.5 h60
  text "Top Layer" at 12804.49,10806.5 h60
  text "1.40mil" at 14594,10806.5 h60
  text "Dielectric1" at 12804.49,10686.5 h60
  text "RO4350B" at 13734.23,10686.5 h60
  text "4.02mil" at 14594,10686.5 h60
  text "4.8" at 15243.84,10686.5 h60
  text "2" at 12394.58,10566.5 h60
  text "L2_GND1" at 12804.49,10566.5 h60
  text "1.40mil" at 14594,10566.5 h60
  text "Dielectric2" at 12804.49,10446.5 h60
  text "185HR" at 13734.23,10446.5 h60
  text "6.66mil" at 14594,10446.5 h60
  text "4.2" at 15243.84,10446.5 h60
  text "3" at 12394.58,10326.5 h60
  text "L3_SIG1" at 12804.49,10326.5 h60
  text "1.40mil" at 14594,10326.5 h60
  text "Dielectric3" at 12804.49,10206.5 h60
  text "185HR" at 13734.23,10206.5 h60
  text "31.50mil" at 14594,10206.5 h60
  text "4.2" at 15243.84,10206.5 h60
  text "4" at 12394.58,10086.5 h60
  text "L4_PWR1" at 12804.49,10086.5 h60
  text "1.40mil" at 14594,10086.5 h60
  text "0.5 Oz + PLATING" at 17009,10025.19 h35
  text "Dielectric4" at 12804.49,9966.5 h60
  text "185HR" at 13734.23,9966.5 h60
  text "7.16mil" at 14594,9966.5 h60
  text "4.2" at 15243.84,9966.5 h60
  text "5" at 12394.58,9846.5 h60
  text "L5_GND2" at 12804.49,9846.5 h60
  text "1.40mil" at 14594,9846.5 h60
  text "Dielectric5" at 12804.49,9726.5 h60
  text "RO4350B" at 13734.23,9726.5 h60
  text "4.02mil" at 14594,9726.5 h60
  text "4.2" at 15243.84,9726.5 h60
  text "6" at 12394.58,9606.5 h60
  text "Bottom Layer" at 12804.49,9606.5 h60
  text "1.40mil" at 14594,9606.5 h60
  text "Bottom Solder" at 12804.49,9486.5 h60
  text "Solder Resist" at 13734.23,9486.5 h60
  text "0.40mil" at 14594,9486.5 h60
  text "3.5" at 15243.84,9486.5 h60
  text "Bottom Overlay" at 12804.49,9366.5 h60
  text ".Layer_Name" at -423,-1858.49 h60
M13 Component Bodies Top:
  text ".Layer_Name" at -423,-1858.49 h60
M14 Component Bodies Bottom:
  text ".Layer_Name" at -423,-1858.49 h60
M15 Courtyards Top:
  text ".Layer_Name" at -423,-1858.49 h60
M16 Courtyards Bottom:
  text ".Layer_Name" at -423,-1858.49 h60
Drill Drawing:
  drawing of 160 lines, arcs and shapes, not listed
  text "Symbol" at 12391.95,9875.88 h72
  text "Quantity" at 12897.82,9875.88 h72
  text "Finished Hole Size" at 13547.65,9875.88 h72
  text "Plated" at 14893.25,9875.88 h72
  text "Hole Type" at 15399.13,9875.88 h72
  text "Drill Layer Pair" at 16132.93,9875.88 h72
  text "Tolerance" at 17632.48,9875.88 h72
  text "8" at 12897.82,9725.88 h60
  text "7.87mil (0.200mm)" at 13547.65,9725.88 h60
  text "PTH" at 14893.25,9725.88 h60
  text "Round" at 15399.13,9725.88 h60
  text "Top Layer - Bottom Layer" at 16132.93,9725.88 h60
  text "+3/-3 mil" at 17632.48,9725.88 h60
  text "34" at 12897.82,9575.88 h60
  text "8.00mil (0.203mm)" at 13547.65,9575.88 h60
  text "PTH" at 14893.25,9575.88 h60
  text "Round" at 15399.13,9575.88 h60
  text "Top Layer - Bottom Layer" at 16132.93,9575.88 h60
  text "+3/-3 mil" at 17632.48,9575.88 h60
  text "DRILL TABLE :" at 12317,9514 h75
  text "188" at 12897.82,9425.88 h60
  text "8.10mil (0.206mm)" at 13547.65,9425.88 h60
  text "PTH" at 14893.25,9425.88 h60
  text "Round" at 15399.13,9425.88 h60
  text "Top Layer - Bottom Layer" at 16132.93,9425.88 h60
  text "+3/-3 mil" at 17632.48,9425.88 h60
  text "542" at 12897.82,9275.88 h60
  text "10.00mil (0.254mm)" at 13547.65,9275.88 h60
  text "PTH" at 14893.25,9275.88 h60
  text "Round" at 15399.13,9275.88 h60
  text "Top Layer - Bottom Layer" at 16132.93,9275.88 h60
  text "+3/-3 mil" at 17632.48,9275.88 h60
  text "A" at 12362.86,9265.9 h66.67
  text "226" at 12897.82,9125.88 h60
  text "12.00mil (0.305mm)" at 13547.65,9125.88 h60
  text "PTH" at 14893.25,9125.88 h60
  text "Round" at 15399.13,9125.88 h60
  text "Top Layer - Bottom Layer" at 16132.93,9125.88 h60
  text "6" at 12897.82,8975.88 h60
  text "29.92mil (0.760mm)" at 13547.65,8975.88 h60
  text "PTH" at 14893.25,8975.88 h60
  text "Slot" at 15399.13,8975.88 h60
  text "Top Layer - Bottom Layer" at 16132.93,8975.88 h60
  text "3" at 12897.82,8825.88 h60
  text "39.76mil (1.010mm)" at 13547.65,8825.88 h60
  text "PTH" at 14893.25,8825.88 h60
  text "Slot" at 15399.13,8825.88 h60
  text "Top Layer - Bottom Layer" at 16132.93,8825.88 h60
  text "15" at 12897.82,8675.88 h60
  text "40.00mil (1.016mm)" at 13547.65,8675.88 h60
  text "PTH" at 14893.25,8675.88 h60
  text "Round" at 15399.13,8675.88 h60
  text "Top Layer - Bottom Layer" at 16132.93,8675.88 h60
  text "+3/-3 mil" at 17632.48,8675.88 h60
  text "19" at 12897.82,8525.88 h60
  text "40.16mil (1.020mm)" at 13547.65,8525.88 h60
  text "PTH" at 14893.25,8525.88 h60
  text "Round" at 15399.13,8525.88 h60
  text "Top Layer - Bottom Layer" at 16132.93,8525.88 h60
  text "+3/-3 mil" at 17632.48,8525.88 h60
  text "10" at 12897.82,8375.88 h60
  text "41.34mil (1.050mm)" at 13547.65,8375.88 h60
  text "PTH" at 14893.25,8375.88 h60
  text "Round" at 15399.13,8375.88 h60
  text "Top Layer - Bottom Layer" at 16132.93,8375.88 h60
  text "+2/-2 mil" at 17632.48,8375.88 h60
  text "12" at 12897.82,8225.88 h60
  text "45.28mil (1.150mm)" at 13547.65,8225.88 h60
  text "PTH" at 14893.25,8225.88 h60
  text "Round" at 15399.13,8225.88 h60
  text "Top Layer - Bottom Layer" at 16132.93,8225.88 h60
  text "8" at 12897.82,8075.88 h60
  text "47.24mil (1.200mm)" at 13547.65,8075.88 h60
  text "PTH" at 14893.25,8075.88 h60
  text "Round" at 15399.13,8075.88 h60
  text "Top Layer - Bottom Layer" at 16132.93,8075.88 h60
  text "+3/-3 mil" at 17632.48,8075.88 h60
  text "2" at 12897.82,7925.88 h60
  text "61.02mil (1.550mm)" at 13547.65,7925.88 h60
  text "PTH" at 14893.25,7925.88 h60
  text "Round" at 15399.13,7925.88 h60
  text "Top Layer - Bottom Layer" at 16132.93,7925.88 h60
  text "+3/-3 mil" at 17632.48,7925.88 h60
  text "16" at 12897.82,7775.88 h60
  text "62.99mil (1.600mm)" at 13547.65,7775.88 h60
  text "NPTH" at 14893.25,7775.88 h60
  text "Round" at 15399.13,7775.88 h60
  text "Top Layer - Bottom Layer" at 16132.93,7775.88 h60
  text "5" at 12897.82,7625.88 h60
  text "62.99mil (1.600mm)" at 13547.65,7625.88 h60
  text "PTH" at 14893.25,7625.88 h60
  text "Round" at 15399.13,7625.88 h60
  text "Top Layer - Bottom Layer" at 16132.93,7625.88 h60
  text "+3/-3 mil" at 17632.48,7625.88 h60
  text "4" at 12897.82,7475.88 h60
  text "125.98mil (3.200mm)" at 13547.65,7475.88 h60
  text "NPTH" at 14893.25,7475.88 h60
  text "Round" at 15399.13,7475.88 h60
  text "Top Layer - Bottom Layer" at 16132.93,7475.88 h60
  text "+2/-2 mil" at 17632.48,7475.88 h60
  text "F" at 12362.86,7465.9 h66.67
  text "1098 Total" at 12897.82,7325.88 h60
  text "Slot definitions :" at 12391.95,7180.91 h60
  text "Routed Path Length" at 13424.64,7180.91 h60
  text "= Calculated from tool start centre position to tool end centre position." at 14527.3,7180.91 h60
  text "Hole Length" at 13424.64,7080.94 h60
  text "= Routed Path Length + Tool Size = Slot length as defined in the PCB layout" at 14117.44,7080.94 h60
  text ".Layer_Name" at -423,-1858.49 h60
M17 Embedded Cavity:
  text ".Layer_Name" at -423,-1858.49 h60
M18 Embedded Assembly:
  text ".Layer_Name" at -423,-1858.49 h60
M19 Embedded Keepout:
  text ".Layer_Name" at -423,-1858.49 h60

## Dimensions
-100,5000 to -100,0 on M2 Board Dimensions
-100,5000 to 5400,5000 on M2 Board Dimensions
16.32,-547.92 to 1016.32,-547.92 on M2 Board Dimensions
